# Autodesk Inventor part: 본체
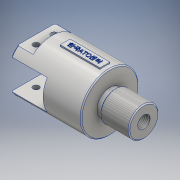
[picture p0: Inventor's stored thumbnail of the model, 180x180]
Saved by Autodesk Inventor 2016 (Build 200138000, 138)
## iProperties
Created: 2019-02
Part Number: 본체
Material: 알루미늄 6061
Document SubType Name: Modeling
Designer: 605-12
Density: 2.7 g/cm^3
Appearance: 알루미늄 - 평지
Mass: 345.889 g
Surface Area: 290.427 cm^2
Volume: 128.107 cm^3
Author: 605-12
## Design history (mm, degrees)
sketch "스케치1"
  geometry: L1 (0, 0)-(0, 29); L2 (0, 29)-(38, 29); L3 (38, 29)-(38, 13); L4 (38, 13)-(43, 13); L5 (43, 13)-(43, 15); L6 (43, 15)-(72, 15); L7 (72, 15)-(72, 0); L8 (72, 0)-(0, 0); L9 (0, 14)-(2.65, 14); L10 (2.65, 14)-(2.65, 16.2); L11 (3.45, 17)-(6.55, 17); L12 (7.35, 16.2)-(7.35, 14); L13 (7.35, 14)-(11.65, 14); L14 (11.65, 14)-(11.65, 16.2); L15 (12.45, 17)-(15.55, 17); L16 (16.35, 16.2)-(16.35, 14); L17 (16.35, 14)-(20, 14); L18 (20, 14)-(20, 16); L19 (20, 16)-(27, 16); L20 (27, 16)-(27, 4); L21 (27, 4)-(72, 4); A1 r 0.8 centre (3.45, 16.2) between (3.45, 17) and (2.65, 16.2); A2 r 0.8 centre (6.55, 16.2) between (7.35, 16.2) and (6.55, 17); A3 r 0.8 centre (12.45, 16.2) between (12.45, 17) and (11.65, 16.2); A4 r 0.8 centre (15.55, 16.2) between (16.35, 16.2) and (15.55, 17); 2 further points
  constraints: 42 end point, 18 perpendicular, 8 point on circle, 8 tangent, 7 point on line, 4 centre point, 3 equal radius, 2 horizontal, 1 vertical
  dimensions: "d21" = 72 distance between parallel lines of L7 L1; "d22" = 26 diameter of L4 L8; "d23" = 5 distance between parallel lines of L5 L3; "d24" = 30 diameter of L6 L8; "d25" = 58 diameter of L2 L8; "d26" = 34 distance between parallel lines of L7 L3; "d27" = 8 diameter of L21 L8; "d28" = 27 distance between parallel lines of L20 L1; "d29" = 7 distance of L18.end L19.end; "d30" = 2.65 distance between parallel lines of L10 L1; "d31" = 28 diameter of L9 L8; "d32" = 34 diameter of L11 L8; "d33" = 28 diameter of L13 L8; "d34" = 28 diameter of L17 L8; "d35" = 7.35 distance between parallel lines of L12 L1; "d36" = 3.65 distance between parallel lines of L16 L18; "d37" = 32 diameter of L19 L8; "d38" = 4.7 distance of point (11.65, 17) point (16.35, 17); "d39" = 0.8 radius of A1
revolve "회전1" sketch "스케치1" stored, may be unused: angle "d40" = 90 deg
sketch "스케치2"
  geometry: L1 (0, 0)-(-36, 0); L2 (-36, 0)-(-36, 29); L3 (-36, 29)-(0, 29); L4 (0, 29)-(0, 0)
  constraints: 8 end point, 2 parallel, 1 horizontal, 1 perpendicular
  dimensions: "d41" = 36 distance of L2.end L3.end; "d42" = 58 diameter of L3 L1
revolve "회전2" sketch "스케치2" stored, may be unused: angle "d43" = 90 deg
node "작업 평면1"
sketch "스케치3"
  geometry: L1 (0, -15)-(44, -15); L2 (44, -15)-(44, 15); L3 (44, 15)-(0, 15); L4 (0, 15)-(0, -15); L5 (36, -29)-(-38, -29) reference; L6 (20, -29)-(40, -29); L7 (40, -29)-(40, -22); L8 (40, -22)-(20, -22); L9 (20, -22)-(20, -29); L10 (36, 29)-(-38, 29) reference; L11 (20, 29)-(40, 29); L12 (40, 29)-(40, 22); L13 (40, 22)-(20, 22); L14 (20, 22)-(20, 29); 2 further points
  constraints: 24 end point, 6 parallel, 4 point on line, 3 horizontal, 3 perpendicular, 1 coincident, 1 midpoint
  dimensions: "d45" = 30 distance of L1.end L2.end; "d47" = 0 distance of point (0, 0) point (0, 0); "d48" = 44 distance of L2.end L3.end; "d49" = 7 distance of L6.end L7.end; "d50" = 7 distance of L11.end L12.end; "d51" = 20 distance from line of point (0, 0) L9; "d52" = 40 distance from line of point (0, 0) L12
extrude "돌출1" cut sketch "스케치3" stored distance "d53" = 10; taper "d54" = 0 deg
node "작업 평면2"
sketch "스케치5"
  geometry: L1 (-36, 24.819)-(-36, -24.819) reference; C1 r 3 at (-27, 9); C2 r 3 at (-27, -9); 1 further point
  constraints: 2 centre point
  dimensions: "d58" = 6 diameter of C1; "d59" = 6 diameter of C2; "d60" = 9 distance from line of L1 C2.centre; "d61" = 9 distance from line of L1 C1.centre; "d62" = 9 vertical distance of point (0, 0) C2.centre; "d63" = 9 vertical distance of point (0, 0) C1.centre
extrude "돌출2" cut sketch "스케치5" stored distance "d64" = 10; taper "d65" = 0 deg
hole "구멍1" diameter "d68" = 12.376; stored, may be unused: countersink angle "d72" = 90 deg, drill point angle "d74" = 118 deg; dims "d66" = 10, "d67" = 10, "d69" = 18, "d70" = 4, "d71" = 2, "d73" = 22
feature "스레드1" dims "d75" = 10, "d76" = 0
node "작업 평면3"
sketch "스케치6"
  geometry: L1 (-7, 5)-(33, 5); L2 (33, 5)-(33, -5); L3 (33, -5)-(-7, -5); L4 (-7, -5)-(-7, 5); L5 (38, -29)-(38, 29) reference; 2 further points
  constraints: 8 end point, 2 parallel, 1 horizontal, 1 horizontal alignment, 1 midpoint, 1 perpendicular
  dimensions: "d78" = 10 distance of L1.end L2.end; "d79" = 40 distance of L1.start L1.end; "d81" = 5 distance between parallel lines of L5 L2
extrude "돌출3" join sketch "스케치6" stored distance "d82" = 10; taper "d83" = 0 deg
sketch "스케치8"
  geometry: L1 (-7, -5)-(-7, 5) reference; L2 (33, -5)-(-7, -5) reference; 2 further points
  constraints: 1 other
  dimensions: "d86" = 20 distance from line of L1 point (13, 0); "d87" = 5 distance from line of L2 point (13, 0)
feature "엠보싱1" sketch "스케치8" dims "d39" = 0.8, "d88" = 0.5, "d89" = 0
chamfer "모따기1" distance "d90" = 1; stored, may be unused: second distance "d91" = 2, angle "d92" = 45 deg
node "솔리드1"
other parameters: "d44" = 29, "d57" = 22
